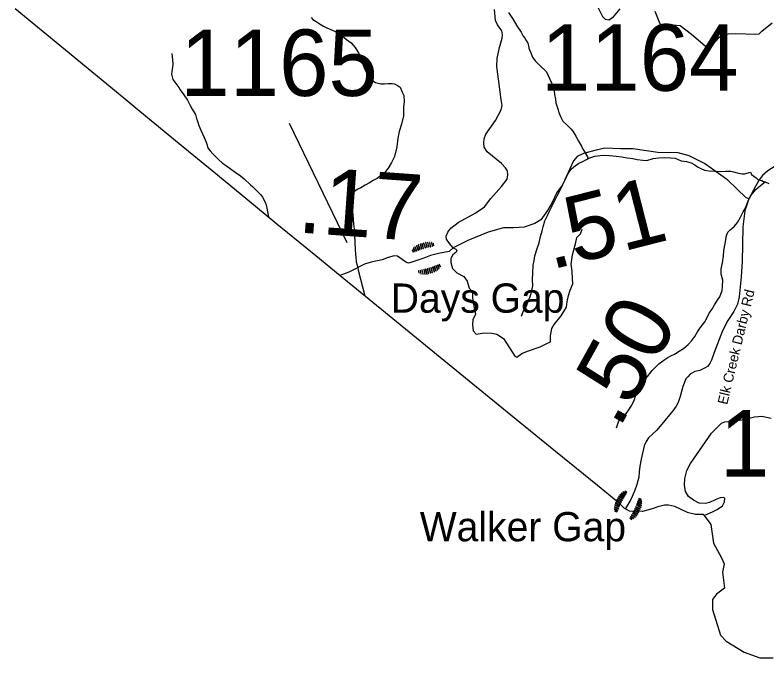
# Model space of a CAD drawing. Extents: x 1248089 to 1457196, y 820910 to 988753.
# Drawn here: x 1250427 to 1256090, y 864614 to 869456 of the extents above; entities that cross this region are included whole.
import ezdxf

# ---------------------------------------------------------------- set-up
doc = ezdxf.new("R2010")
doc.units = 0
for name, color, linetype in [('Exist Boundary Political CountyLine', 7, 'Continuous'), ('Exist Geographical Mountain Gap CELL', 7, 'Continuous'), ('Exist Geographical Mountain Summit Label', 7, 'Continuous'), ('Exist Hydrographic Creek Single Shore', 7, 'Continuous'), ('Exist Hydrographic Misc Water Feature', 7, 'Continuous'), ('Exist Road Non-System Type 51', 7, 'Continuous'), ('Exist Road Secondary Type 41 Attributed', 7, 'Continuous'), ('Exist Road Secondary Type 51 Attributed', 7, 'Continuous'), ('Exist Road Secondary Type 51 Label', 7, 'Continuous'), ('Prop GRAU CAT1 Cell', 7, 'Continuous'), ('Prop Lane Lines', 7, 'Continuous')]:
    doc.layers.add(name, color=color, linetype=linetype)

msp = doc.modelspace()

# ---------------------------------------------------------------- linework, layer by layer
at = {"layer": 'Exist Boundary Political CountyLine'}
for points in [[(1250427.4, 869505.7), (1250806.4, 869194.4), (1251246.4, 868833), (1251367.4, 868732.8), (1251706.4, 868454.7), (1251924.4, 868275.4), (1252165.4, 868077), (1252399.4, 867884.8), (1252692.4, 867644.2), (1252875.5, 867493.6), (1253367.5, 867092.1), (1253600.5, 866901.7), (1253874.5, 866678.1), (1254229.5, 866389.1), (1254497.5, 866172.8), (1254813.5, 865915.1), (1254966.5, 865789.8), (1255013.5, 865746.1), (1255051.7, 865722.4)], [(1255051.7, 865722.4), (1255150.2, 865718.7), (1255155, 865719.3), (1255228.1, 865739.9), (1255279, 865757.4), (1255319.5, 865767), (1255349.8, 865767), (1255394.3, 865758.2), (1255488.5, 865712.1), (1255552.1, 865696.2), (1255609.3, 865696.2), (1255666.5, 865619.8), (1255688.8, 865479.8), (1255749.2, 865368.5), (1255768.3, 865323.9), (1255755.6, 865260.3), (1255771.5, 865139.4), (1255711, 865094.8), (1255679.2, 865053.5), (1255679.2, 864980.3), (1255741.3, 864786.2), (1255782.6, 864741.7), (1255919.3, 864658.9), (1256037, 864614.4), (1256136.6, 864616.5)]]:
    msp.add_lwpolyline(points, dxfattribs=at)
at = {"layer": 'Exist Geographical Mountain Gap CELL'}
for points in [[(1253515.8, 867702.5), (1253518.5, 867703.3), (1253507.3, 867739.4), (1253504.6, 867738.6)], [(1253529.3, 867706.7), (1253532.1, 867707.5), (1253520.9, 867743.6), (1253518.1, 867742.8)], [(1253540.7, 867709), (1253543.4, 867709.8), (1253535.5, 867745.2), (1253532.7, 867744.4)], [(1253555, 867711), (1253557.7, 867711.8), (1253550.5, 867744.4), (1253547.8, 867743.6)], [(1253566.5, 867741.7), (1253566.1, 867742.9), (1253563.4, 867742), (1253568.4, 867716.4), (1253568.8, 867715.2), (1253571.5, 867716.1)], [(1253426.6, 867671.1), (1253429.3, 867672), (1253425, 867679.5), (1253420.7, 867687.1), (1253418, 867686.3), (1253422.3, 867678.6)], [(1253430, 867699.4), (1253429.6, 867700.5), (1253426.9, 867699.7), (1253437.3, 867675.7), (1253437.7, 867674.6), (1253440.4, 867675.4)], [(1253451.2, 867678.8), (1253453.9, 867679.6), (1253441.4, 867710.6), (1253438.6, 867709.7)], [(1253464.3, 867685.3), (1253467, 867686.1), (1253453.6, 867719.8), (1253450.9, 867719)], [(1253474.7, 867689.8), (1253477.5, 867690.6), (1253466.3, 867726.7), (1253463.5, 867725.9)], [(1253488.5, 867694), (1253491.2, 867694.9), (1253480, 867731), (1253477.3, 867730.1)], [(1253502.1, 867698.2), (1253504.7, 867699.1), (1253493.5, 867735.2), (1253490.9, 867734.3)], [(1253579.6, 867718.6), (1253582.3, 867719.4), (1253580, 867735.5), (1253577.3, 867734.7)], [(1253598.4, 867569.2), (1253595.7, 867568.4), (1253608, 867537.4), (1253610.7, 867538.2)], [(1253619.4, 867548.4), (1253619.8, 867547.3), (1253622.5, 867548.1), (1253612.3, 867572.2), (1253611.9, 867573.3), (1253609.2, 867572.5)], [(1253623, 867576.7), (1253620.3, 867575.8), (1253624.5, 867568.3), (1253628.8, 867560.7), (1253631.5, 867561.5), (1253627.3, 867569.1)], [(1253469.7, 867530.3), (1253467, 867529.5), (1253469.1, 867513.4), (1253471.8, 867514.2)], [(1253482.6, 867507.1), (1253483, 867506), (1253485.7, 867506.8), (1253480.9, 867532.5), (1253480.5, 867533.6), (1253477.8, 867532.8)], [(1253494.3, 867537.8), (1253491.6, 867537), (1253498.6, 867504.3), (1253501.3, 867505.1)], [(1253508.6, 867539.6), (1253505.9, 867538.8), (1253513.6, 867503.4), (1253516.4, 867504.2)], [(1253520, 867541.9), (1253517.3, 867541), (1253528.2, 867504.9), (1253531, 867505.7)], [(1253533.6, 867546), (1253530.9, 867545.1), (1253541.8, 867509), (1253544.5, 867509.8)], [(1253547.4, 867550.1), (1253544.7, 867549.3), (1253555.6, 867513.1), (1253558.3, 867513.9)], [(1253560.9, 867554.2), (1253558.2, 867553.4), (1253569.1, 867517.2), (1253571.9, 867518)], [(1253574.8, 867558.4), (1253572, 867557.6), (1253582.9, 867521.4), (1253585.7, 867522.2)], [(1253585.3, 867562.8), (1253582.6, 867562), (1253595.7, 867528.2), (1253598.4, 867529)], [(1255033.2, 865857.8), (1255034.5, 865860.3), (1255021.4, 865869.9), (1255020.1, 865867.4)], [(1255000.4, 865800.9), (1255001.7, 865803.4), (1254968, 865820.5), (1254966.7, 865818)], [(1255006.8, 865813.5), (1255008.1, 865816), (1254974.4, 865833.1), (1254973.1, 865830.6)], [(1255013.1, 865823.3), (1255014.4, 865825.8), (1254983.5, 865844.7), (1254982.1, 865842.1)], [(1255021.6, 865834.9), (1255022.9, 865837.4), (1254994.5, 865855), (1254993.2, 865852.5)], [(1255007.5, 865864.5), (1255006.5, 865865.1), (1255005.2, 865862.5), (1255027.1, 865848.3), (1255028.1, 865847.7), (1255029.4, 865850.2)], [(1255126.3, 865814.9), (1255125.1, 865812.3), (1255133.5, 865810.6), (1255142.1, 865808.8), (1255143.3, 865811.3), (1255134.7, 865813.2)], [(1254976.9, 865751.9), (1254978.2, 865754.4), (1254944.7, 865768.2), (1254943.4, 865765.7)], [(1254981, 865762.5), (1254982.3, 865765.1), (1254948.6, 865782.2), (1254947.3, 865779.6)], [(1254987.5, 865775.4), (1254988.8, 865777.9), (1254955.1, 865795), (1254953.8, 865792.4)], [(1254993.9, 865788), (1254995.2, 865790.5), (1254961.5, 865807.6), (1254960.2, 865805.1)], [(1255108.1, 865766.6), (1255106.9, 865764), (1255141.3, 865748.3), (1255142.5, 865751)], [(1255111.8, 865777.4), (1255110.6, 865774.8), (1255144.7, 865762.4), (1255145.8, 865765)], [(1255115.6, 865791.5), (1255114.4, 865788.9), (1255145.9, 865777.7), (1255147.1, 865780.3)], [(1255145.1, 865793.6), (1255146.2, 865793.1), (1255147.4, 865795.7), (1255122.5, 865803.9), (1255121.5, 865804.4), (1255120.3, 865801.8)], [(1254942.9, 865737.1), (1254941.9, 865737.6), (1254940.6, 865735.1), (1254965, 865725.9), (1254966.1, 865725.3), (1254967.4, 865727.9)], [(1254972.5, 865738), (1254973.7, 865740.5), (1254942.8, 865753), (1254941.5, 865750.5)], [(1254960.8, 865715), (1254962.1, 865717.5), (1254953.7, 865719.6), (1254945.2, 865721.8), (1254944, 865719.3), (1254952.5, 865717.1)], [(1255078.6, 865704.5), (1255077.4, 865702), (1255109.1, 865684.4), (1255110.3, 865687)], [(1255084.5, 865714.6), (1255083.3, 865712), (1255117.7, 865696.3), (1255118.9, 865698.9)], [(1255090.3, 865727.5), (1255089.2, 865724.9), (1255123.6, 865709.2), (1255124.7, 865711.8)], [(1255096.3, 865740.6), (1255095.1, 865738), (1255129.5, 865722.4), (1255130.7, 865724.9)], [(1255102.2, 865753.5), (1255101, 865750.9), (1255135.4, 865735.2), (1255136.6, 865737.8)], [(1255059.9, 865669.2), (1255058.8, 865666.6), (1255072.3, 865657.6), (1255073.4, 865660.1)], [(1255085.9, 865663.6), (1255087, 865663.1), (1255088.2, 865665.7), (1255065.7, 865679), (1255064.6, 865679.5), (1255063.4, 865676.9)], [(1255070.6, 865692.6), (1255069.4, 865690), (1255098.5, 865673.7), (1255099.7, 865676.2)]]:
    msp.add_lwpolyline(points, close=True, dxfattribs=at)
at = {"layer": 'Exist Hydrographic Creek Single Shore'}
for points in [[(1254742.8, 868375.3), (1254762.9, 868382.8), (1254793.4, 868393.9), (1254833.4, 868399), (1254869.5, 868402), (1254905.4, 868399.1), (1254955.5, 868393.8), (1254997.3, 868388.7), (1255037.2, 868381.7), (1255081, 868376.5), (1255112.8, 868367.7), (1255154.7, 868362.7), (1255184.7, 868361.8), (1255233.1, 868374.7), (1255273.3, 868381.5), (1255315.4, 868384.5), (1255367.3, 868381.1), (1255399.3, 868378.3), (1255444.8, 868359.2), (1255484.7, 868352.1), (1255518.4, 868343.3), (1255546.1, 868328.5), (1255567.7, 868311.9), (1255591.4, 868299.3), (1255619.2, 868288.5), (1255652.9, 868281.7), (1255696.9, 868280.5), (1255740.9, 868277.5), (1255781.1, 868280.4), (1255819.1, 868279.4), (1255838.9, 868274.9), (1255866.8, 868268.2), (1255902.4, 868259.8), (1255922.2, 868259.8), (1255966.6, 868273.4), (1255974.9, 868254.5), (1256009.1, 868229.6), (1256024.7, 868214.6)], [(1254956.8, 866348.2), (1254969.6, 866384), (1254976, 866399.8), (1254982.4, 866411.7), (1255009.1, 866439.1), (1255031.6, 866458.4), (1255050.3, 866481.9), (1255066.9, 866509.6), (1255090.1, 866553.1), (1255103.1, 866592.8), (1255109.7, 866610.5), (1255120.3, 866640.3), (1255137.1, 866670), (1255164, 866701.2), (1255190.9, 866734.5), (1255226, 866779.7), (1255248.6, 866801.1), (1255275.2, 866828.5), (1255314.1, 866857.5), (1255342.6, 866876.8), (1255371, 866892), (1255393.3, 866903.4), (1255429.8, 866924.5), (1255462.3, 866943.7), (1255497.2, 866974.8), (1255524, 867006.1), (1255546.8, 867035.6), (1255567.7, 867071), (1255586.5, 867100.6), (1255621.8, 867145.8), (1255642.7, 867183.2), (1255653.3, 867206.9), (1255680.3, 867246.3), (1255695.1, 867273.9), (1255722.1, 867315.3), (1255734.7, 867334.9), (1255751.9, 867382.5), (1255756.7, 867412.5), (1255757.8, 867460.4), (1255745.1, 867504.8), (1255746.1, 867544.8), (1255755.3, 867590.6), (1255762.6, 867640.5), (1255765.6, 867682.4), (1255774.9, 867736.2), (1255779.8, 867764), (1255786.6, 867795.9), (1255795.2, 867821.7), (1255813.7, 867839.3), (1255826, 867848.9), (1255846.5, 867866.4), (1255869.3, 867893.9), (1255892.2, 867933.3), (1255911.2, 867974.8), (1255919.6, 867986.6), (1255934.4, 868016.2), (1255949.3, 868055.9), (1255960, 868077.6), (1255972.5, 868099.4), (1256005.7, 868142.5), (1256042.4, 868171.6), (1256075.7, 868200.8)], [(1256024.7, 868214.6), (1256052.7, 868209.2), (1256064.4, 868202.7), (1256075.7, 868200.8)], [(1256075.7, 868200.8), (1256104, 868188)]]:
    msp.add_lwpolyline(points, dxfattribs=at)
at = {"layer": 'Exist Hydrographic Misc Water Feature'}
for points in [[(1252656.6, 869437.9), (1252670.3, 869421.4), (1252695.9, 869406.8), (1252725.4, 869388), (1252751, 869371.3), (1252776.8, 869358.6), (1252824.2, 869339.4), (1252861.9, 869322.4), (1252885.5, 869305.8), (1252905, 869287.3), (1252924.6, 869272.8), (1252958, 869247.9), (1252989, 869211.1), (1253015.9, 869166.4), (1253035.1, 869133.9), (1253042.4, 869105.7), (1253049.7, 869077.5), (1253064.8, 869041), (1253074.3, 869020.8), (1253087.4, 868990.4), (1253103, 868972), (1253122.7, 868959.5), (1253142.4, 868948.9), (1253182.2, 868937.8), (1253210.2, 868937.2), (1253238.2, 868940.4), (1253268.3, 868941.7), (1253284.3, 868937.2), (1253313.9, 868922.5), (1253327.6, 868914.1), (1253342.7, 868875.7), (1253356, 868849.4), (1253357, 868805.3), (1253353.8, 868761.4), (1253352, 868697.4), (1253338.4, 868633.6), (1253321.1, 868580), (1253309.7, 868528.3), (1253302, 868464.5), (1253284.2, 868390.9), (1253263, 868345.3), (1253237.9, 868304), (1253211, 868266.7), (1253155.8, 868226.1), (1253125.5, 868210.8), (1253097, 868193.6), (1253064.5, 868174.4), (1253032, 868155.3), (1253003.6, 868141.9), (1252985.2, 868128.4), (1252972.7, 868108.7), (1252961.9, 868081), (1252960.8, 868036.9), (1252965.8, 867998.8), (1252970.6, 867950.7), (1252976.9, 867884.4), (1252981.8, 867844.3), (1252984.7, 867800.2), (1252985.3, 867744.1), (1252988, 867690.1), (1252991.1, 867656), (1252994.4, 867631.8), (1252997.6, 867597.7), (1253004.8, 867571.5), (1253008.3, 867549.4), (1253012, 867535.3), (1253060.9, 867342.3)], [(1254144.7, 869475.5), (1254179.4, 869422.5), (1254206.2, 869373.9), (1254238.9, 869326.9), (1254254.2, 869296.5), (1254267.8, 869282.1), (1254277.2, 869263.9), (1254288.8, 869243.6), (1254294.5, 869225.4), (1254298, 869207.4), (1254310.9, 869171), (1254324.2, 869138.6), (1254343.4, 869110.1), (1254364.9, 869091.5), (1254390.3, 869066.8), (1254415.8, 869044.2), (1254429.4, 869027.9), (1254467.3, 868944.8), (1254482.6, 868916.3), (1254487.7, 868884.2), (1254489.1, 868858.2), (1254498.1, 868821.9), (1254501.5, 868793.8), (1254518.1, 868743.3), (1254523.5, 868723.1), (1254534.8, 868692.8), (1254554, 868656.3), (1254585.2, 868627.5), (1254612.4, 868598.8), (1254628.1, 868582.4), (1254651.1, 868543.7), (1254672.1, 868507.2), (1254693.2, 868468.7), (1254702.5, 868446.3), (1254714.2, 868430), (1254739, 868387.4), (1254742.8, 868375.3)], [(1251609, 869166.7), (1251613.8, 869118.5), (1251615, 869086.4), (1251614.4, 869064.5), (1251607.6, 869030.5), (1251606.9, 869010.5), (1251615.9, 868970.3), (1251639.1, 868939.7), (1251660.4, 868911.1), (1251672, 868892.8), (1251699, 868854.1), (1251726, 868815.4), (1251743.1, 868780.9), (1251760.3, 868748.5), (1251767.9, 868734.2), (1251787.3, 868707.7), (1251794.6, 868677.5), (1251802.1, 868657.3), (1251811.2, 868625), (1251826.3, 868588.6), (1251850.8, 868533.9), (1251865.9, 868499.5), (1251880.8, 868451.1), (1251896.3, 868432.7), (1251917.7, 868410.1), (1251931.3, 868395.8), (1251960.7, 868369), (1251989.9, 868340.2), (1252019.4, 868319.4), (1252086.3, 868273.7), (1252125.5, 868244.7), (1252153, 868221.9), (1252200, 868176.7), (1252219.5, 868162.1), (1252256.6, 868125.2), (1252278.1, 868102.7), (1252291.5, 868084.2), (1252310.7, 868047.7), (1252318.1, 868025.6), (1252337.5, 867935.7)], [(1254241.9, 867187.3), (1254252.6, 867215.1), (1254261, 867238.9), (1254279.8, 867264.4), (1254290.9, 867304.2), (1254303.5, 867329.8), (1254314.4, 867359.6), (1254325.8, 867417.4), (1254325.1, 867465.4), (1254328.2, 867513.3), (1254329.7, 867571.4), (1254336.7, 867607.1), (1254341.6, 867643.1), (1254363.4, 867706.6), (1254374.2, 867740.3), (1254385.3, 867788), (1254396.6, 867831.8), (1254405.3, 867861.6), (1254418.4, 867907.3), (1254437.6, 867946.8), (1254452.5, 867980.4), (1254473.5, 868019.9), (1254496.5, 868065.3), (1254511.4, 868095), (1254540.9, 868152.3), (1254553.6, 868180), (1254570.6, 868215.5), (1254583.3, 868243.2), (1254591.6, 868257.1), (1254608.3, 868284.6), (1254616.6, 868294.5), (1254635.1, 868312), (1254673.8, 868341), (1254704.2, 868354.3), (1254730.6, 868369.5), (1254742.8, 868375.3)]]:
    msp.add_lwpolyline(points, dxfattribs=at)
at = {"layer": 'Exist Road Non-System Type 51'}
for points in [[(1254813.9, 869520.5), (1254852.8, 869444.6), (1254871.6, 869425.9), (1254898.8, 869420.1), (1254935.8, 869443.4), (1254984.4, 869501.8)], [(1255247, 869486.2), (1255270.3, 869422), (1255287.8, 869379.2), (1255324.7, 869361.7), (1255385, 869381.2), (1255435.6, 869377.3), (1255521.2, 869311.1), (1255643.7, 869209.9)], [(1255643.7, 869209.9), (1255673.7, 869216.5), (1255697.7, 869252.5), (1255731.7, 869288.5), (1255755.7, 869308.6), (1255797.7, 869314.6), (1255855.7, 869316.6), (1256005.7, 869312.6), (1256031.7, 869314.6), (1256051.7, 869334.6), (1256129.7, 869396.6)], [(1253727.2, 867702.3), (1253747.2, 867694), (1253755, 867686.2), (1253749.1, 867670.7), (1253723.8, 867649.3), (1253710.2, 867622), (1253708.3, 867592.8), (1253721.9, 867548.1), (1253755, 867515), (1253807.5, 867487.7), (1253832.7, 867450.8), (1253848.3, 867400.2), (1253873.6, 867372.9), (1253873.6, 867324.2), (1253885.3, 867250.3), (1253895, 867203.6), (1253875.5, 867160.8), (1253871.6, 867123.8), (1253877.5, 867077.1), (1253900.8, 867053.7), (1253961.1, 867063.5), (1254019.4, 867061.5), (1254056.4, 867051.8), (1254105, 867020.6), (1254190.6, 866886.4), (1254206.2, 866880.5), (1254245, 866907.8), (1254285.9, 866925.3), (1254381.2, 866956.4), (1254431.7, 866981.7), (1254459, 866995.3), (1254460.9, 867040.1), (1254470.6, 867094.6), (1254488.1, 867125.7), (1254540.7, 867191.9), (1254581.5, 867256.1), (1254585.4, 867295.1), (1254595.1, 867343.7), (1254608.7, 867384.6), (1254628.2, 867431.3), (1254626.2, 867470.2), (1254622.3, 867526.7), (1254616.5, 867581.1), (1254626.2, 867649.3), (1254651.2, 867743.5), (1254658.9, 867780.5), (1254686.2, 867807.7), (1254699.8, 867844.7)], [(1255613.8, 865690.2), (1255634.4, 865695.6), (1255684.8, 865716.2), (1255714.6, 865732.3), (1255755.9, 865759.8), (1255769.6, 865789.6), (1255771.9, 865817.1), (1255760.4, 865824), (1255739.8, 865819.4), (1255737.5, 865819.4), (1255700.8, 865805.7), (1255657.3, 865785), (1255627.5, 865778.1), (1255579.3, 865780.4), (1255538.1, 865803.4), (1255499.1, 865830.9), (1255476.2, 865867.6), (1255469.3, 865915.8), (1255471.6, 865966.3), (1255487.7, 866025.9), (1255515.2, 866078.7), (1255673.3, 866308.1), (1255749, 866383.8), (1255771.9, 866392.9), (1255820, 866395.2), (1255916.3, 866411.3), (1255996.5, 866429.6), (1256051.6, 866434.2), (1256122.6, 866420.5)]]:
    msp.add_lwpolyline(points, dxfattribs=at)
at = {"layer": 'Exist Road Secondary Type 41 Attributed'}
for points in [[(1253727.2, 867702.3), (1253699.6, 867736.9), (1253677, 867768.7), (1253674.5, 867792.1), (1253686.2, 867820.5), (1253709.6, 867851.5), (1253764.8, 867894.1), (1253892.6, 867963), (1253963.4, 868012.5), (1254010.6, 868073.9), (1254090.8, 868163.7), (1254133.3, 868220.3), (1254138, 868253.4), (1254135.7, 868284.1), (1254121.5, 868305.4), (1254090.8, 868338.4), (1253981.9, 868425.3), (1253959.3, 868462.1), (1253958.5, 868493.8), (1253961, 868524), (1253972.7, 868558.2), (1254046.7, 868662.8), (1254087.7, 868741.4), (1254096, 868775.7), (1254089.4, 868819.2), (1254056.3, 869069.3), (1254058.8, 869129.5), (1254075.1, 869212.3), (1254095.2, 869280.9), (1254098.6, 869306), (1254093.5, 869336.9), (1254060, 869381.8), (1254047.1, 869415.6), (1254039.6, 869497.5)], [(1255954.1, 868071.1), (1255930.1, 868082.6), (1255795.7, 868211.5), (1255619.6, 868338.5), (1255504.1, 868395.3), (1255422.6, 868418.1), (1255269.3, 868419.9), (1255079, 868448.2), (1254988.2, 868448.2), (1254868.9, 868453.9), (1254804.5, 868438.7), (1254707.9, 868414.1), (1254660.6, 868391.3), (1254634.1, 868357.2), (1254549.3, 868176.3), (1254507.6, 868119.4), (1254471.7, 868043.6), (1254437.6, 867984.9), (1254386.5, 867914.8), (1254342.9, 867886.4), (1254261.5, 867859.8), (1254181.9, 867854.1), (1254106.2, 867854.1), (1253990.7, 867820), (1253837.3, 867759.4), (1253727.2, 867702.3)], [(1253727.2, 867702.3), (1253697.5, 867675.8), (1253617.2, 867659.9), (1253557, 867644.1), (1253506.8, 867625.7), (1253415.2, 867593.9), (1253391.4, 867588.4), (1253371.2, 867593.9), (1253343.7, 867616), (1253308.8, 867639.9), (1253283.1, 867641.7), (1253237.3, 867630.7), (1253191.4, 867612.3), (1253109.5, 867594.7), (1253060.2, 867578.8), (1252940.5, 867519.4), (1252872.7, 867495.9)]]:
    msp.add_lwpolyline(points, dxfattribs=at)
at = {"layer": 'Exist Road Secondary Type 51 Attributed'}
for points in [[(1258291.7, 868873.2), (1258244.4, 868782.3), (1258176.2, 868710.3), (1258115.6, 868630.7), (1258083.4, 868592.8), (1258015.2, 868551.1), (1257860.8, 868510.1), (1257701.8, 868489.3), (1257586.3, 868489.3), (1257525.7, 868491.2), (1257368.5, 868441.9), (1257292.8, 868430.6), (1257231.5, 868439.5), (1257115.9, 868509.7), (1257032.6, 868528.6), (1256975.8, 868534.3), (1256818.7, 868513.4), (1256689.9, 868507.8), (1256508.1, 868509.7), (1256438.1, 868492.6), (1256310.3, 868417.6), (1256096.9, 868282.5), (1256057.8, 868247.3), (1256032.3, 868215)], [(1256032.3, 868215), (1256006.9, 868169), (1255954.1, 868071.1)], [(1255954.1, 868071.1), (1255924.6, 867982.5), (1255908.1, 867861.5), (1255903.9, 867597.2), (1255895.2, 867483.5), (1255881.8, 867333.7), (1255867.6, 867278.5), (1255840, 867223.3), (1255796, 867155.6), (1255756.7, 867077), (1255692.7, 866913.9), (1255671.8, 866856.2), (1255660.1, 866831.1), (1255641.7, 866810.2), (1255624.2, 866798.4), (1255584, 866780), (1255547.2, 866770.8), (1255512.9, 866750.8), (1255494.5, 866732.4), (1255478.6, 866715.6), (1255457.3, 866657.9), (1255437.2, 866582.7), (1255421.3, 866538.3), (1255405.4, 866510.7), (1255382, 866474.8), (1255321.8, 866402.8), (1255262, 866330.9), (1255198.4, 866271.5), (1255180, 866243.9), (1255165.8, 866211.3), (1255142.8, 866111.8), (1255133.6, 866059.9), (1255128.6, 866015.6), (1255124.4, 865977.1), (1255110.2, 865921.9), (1255091.8, 865870.9), (1255065, 865808.1), (1255025, 865739)]]:
    msp.add_lwpolyline(points, dxfattribs=at)
at = {"layer": 'Prop Lane Lines'}
msp.add_line((1252929.6, 867740.2), (1252494, 868640.3), dxfattribs=at)

# ---------------------------------------------------------------- texts
at = {"layer": 'Exist Geographical Mountain Summit Label'}
for s, p in [('Days Gap', (1253257.4, 867214.7)), ('Walker Gap', (1253475.8, 865493.1))]:
    msp.add_text(s, height=220, dxfattribs=at).set_placement(p)
at = {"layer": 'Exist Road Secondary Type 51 Label'}
msp.add_text('Elk Creek Darby Rd', height=75, rotation=76.4455, dxfattribs=at).set_placement((1255790.3, 866517.5))
at = {"layer": 'Prop GRAU CAT1 Cell'}
for s, rotation, p in [('.17', 355.9124, (1252549.6, 867819.3)), ('.51', 14.3113, (1254463.1, 867536.7)), ('.50', 60.9471, (1254975.7, 866333.6))]:
    msp.add_text(s, height=500, rotation=rotation, dxfattribs=at).set_placement(p)
at = {"layer": 'Prop Lane Lines'}
for s, p in [('1164', (1254388.6, 868886)), ('1165', (1251672.6, 868847)), ('1162', (1255735.5, 865980.9))]:
    msp.add_text(s, height=500, dxfattribs=at).set_placement(p)

doc.saveas('drawing.dxf')
